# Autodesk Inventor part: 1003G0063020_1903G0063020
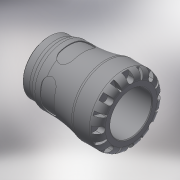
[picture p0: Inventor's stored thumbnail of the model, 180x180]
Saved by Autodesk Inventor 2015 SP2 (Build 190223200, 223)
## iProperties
Created: 2016-12
Part Number: 1003G0063020_1903G0063020
Material: Generic
Description: PLASSON FEMALE ADAPTOR 63x2" SERIES 1
Document SubType Name: Modeling
Designer: KIM
Mass: 485.003 g
Surface Area: 735.98 cm^2
Volume: 485.003 cm^3
Density: 1 g/cm^3
Appearance: Default
Author: KIM
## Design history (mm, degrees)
derived "1003G.ipt"
feature "Solid1::1003G.ipt"
tag "TaggingFeature1"
body "Solid1"
other parameters: "d0" = 129, "d1" = 39.9, "d2" = 63, "d3" = 78.75, "d4" = 103, "d6" = 95, "d8" = 87.55, "d13" = 9.7, "d14" = 9.7, "d15" = 0, "d17" = 360 deg, "d19" = 8 deg, "d20" = 1.26, "d21" = 1.26, "d22" = 8 deg, "d24" = 0, "d26" = 360 deg, "d32" = 10.3, "d33" = 10.3, "d39" = 1.69968, "d42" = 56.656, "d43" = 80.34, "d46" = 5.25, "d47" = 23, "d48" = 53.8232, "d50" = 3.63, "d51" = 1.03, "d54" = 22.05, "d55" = 13.86, "d57" = 19.012, "d58" = 0, "d68" = 360 deg, "d72" = 1.26, "d74" = 0, "d76" = 18.7425, "d_" = 63, "E_" = 103, "H_" = 129, "l_" = 95, "G_" = 56.656, "l_2" = 23, "d9" = 12.125, "d11" = 103, "d12" = 78.75, "d49" = 11
